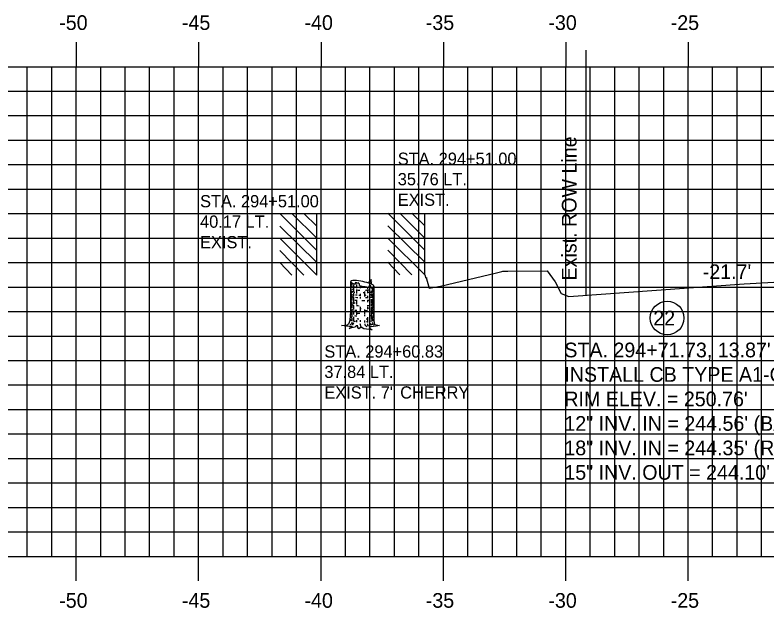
# Model space of a CAD drawing. Extents: x 859352 to 859522, y 366268 to 366378.
# Drawn here: x 859382.63 to 859413.35, y 366305.13 to 366329.35 of the extents above; entities that cross this region are included whole.
import ezdxf

# ---------------------------------------------------------------- set-up
doc = ezdxf.new("R2010")
doc.units = 0
for name, color, linetype in [('D_Drainage_Text', 7, 'Continuous'), ('D_Text_Monospaced', 7, 'Continuous'), ('D_Text_Standard', 7, 'Continuous'), ('E_ROW_Line', 7, 'Continuous'), ('H_V ANNOTATION', 7, 'Continuous'), ('MAJOR', 7, 'Continuous'), ('MINOR', 7, 'Continuous'), ('S_Buildings', 7, 'Continuous'), ('S_Roadway_Centerline', 7, 'Continuous'), ('S_Trees_Decid_NonPay', 7, 'Continuous')]:
    doc.layers.add(name, color=color, linetype=linetype)

msp = doc.modelspace()

# ---------------------------------------------------------------- linework, layer by layer
at = {"layer": 'D_Drainage_Text'}
msp.add_circle((859409.269, 366316.971), 0.687, dxfattribs=at)
at = {"layer": 'E_ROW_Line'}
msp.add_line((859405.968, 366317.905), (859405.968, 366327.905), dxfattribs=at)
at = {"layer": 'MAJOR'}
for p, q in [((859385.129, 366328.238), (859385.129, 366327.236)), ((859390.129, 366328.238), (859390.129, 366327.236)), ((859395.129, 366328.238), (859395.129, 366327.236)), ((859400.129, 366328.238), (859400.129, 366327.236)), ((859405.129, 366328.238), (859405.129, 366327.236)), ((859410.129, 366328.238), (859410.129, 366327.236)), ((859365.129, 366327.236), (859505.129, 366327.236)), ((859365.129, 366327.236), (859505.129, 366327.236)), ((859385.129, 366307.236), (859385.129, 366327.236)), ((859390.129, 366307.236), (859390.129, 366327.236)), ((859395.129, 366307.236), (859395.129, 366327.236)), ((859400.129, 366307.236), (859400.129, 366327.236)), ((859405.129, 366307.236), (859405.129, 366327.236)), ((859410.129, 366307.236), (859410.129, 366327.236)), ((859365.129, 366322.236), (859505.129, 366322.236)), ((859365.129, 366317.236), (859505.129, 366317.236)), ((859365.129, 366312.236), (859505.129, 366312.236)), ((859365.129, 366307.236), (859505.129, 366307.236)), ((859365.129, 366307.236), (859505.129, 366307.236)), ((859385.129, 366306.234), (859385.129, 366307.236)), ((859390.129, 366306.234), (859390.129, 366307.236)), ((859395.129, 366306.234), (859395.129, 366307.236)), ((859400.129, 366306.234), (859400.129, 366307.236)), ((859405.129, 366306.234), (859405.129, 366307.236)), ((859410.129, 366306.234), (859410.129, 366307.236))]:
    msp.add_line(p, q, dxfattribs=at)
at = {"layer": 'MINOR'}
for p, q in [((859383.129, 366307.236), (859383.129, 366327.236)), ((859384.129, 366307.236), (859384.129, 366327.236)), ((859386.129, 366307.236), (859386.129, 366327.236)), ((859387.129, 366307.236), (859387.129, 366327.236)), ((859388.129, 366307.236), (859388.129, 366327.236)), ((859389.129, 366307.236), (859389.129, 366327.236)), ((859391.129, 366307.236), (859391.129, 366327.236)), ((859392.129, 366307.236), (859392.129, 366327.236)), ((859393.129, 366307.236), (859393.129, 366327.236)), ((859394.129, 366307.236), (859394.129, 366327.236)), ((859396.129, 366307.236), (859396.129, 366327.236)), ((859397.129, 366307.236), (859397.129, 366327.236)), ((859398.129, 366307.236), (859398.129, 366327.236)), ((859399.129, 366307.236), (859399.129, 366327.236)), ((859401.129, 366307.236), (859401.129, 366327.236)), ((859402.129, 366307.236), (859402.129, 366327.236)), ((859403.129, 366307.236), (859403.129, 366327.236)), ((859404.129, 366307.236), (859404.129, 366327.236)), ((859406.129, 366307.236), (859406.129, 366327.236)), ((859407.129, 366307.236), (859407.129, 366327.236)), ((859408.129, 366307.236), (859408.129, 366327.236)), ((859409.129, 366307.236), (859409.129, 366327.236)), ((859411.129, 366307.236), (859411.129, 366327.236)), ((859412.129, 366307.236), (859412.129, 366327.236)), ((859413.129, 366307.236), (859413.129, 366327.236)), ((859365.129, 366326.236), (859505.129, 366326.236)), ((859365.129, 366325.236), (859505.129, 366325.236)), ((859365.129, 366324.236), (859505.129, 366324.236)), ((859365.129, 366323.236), (859505.129, 366323.236)), ((859365.129, 366321.236), (859505.129, 366321.236)), ((859365.129, 366320.236), (859505.129, 366320.236)), ((859365.129, 366319.236), (859505.129, 366319.236)), ((859365.129, 366318.236), (859505.129, 366318.236)), ((859365.129, 366316.236), (859505.129, 366316.236)), ((859365.129, 366315.236), (859505.129, 366315.236)), ((859365.129, 366314.236), (859505.129, 366314.236)), ((859365.129, 366313.236), (859505.129, 366313.236)), ((859365.129, 366311.236), (859505.129, 366311.236)), ((859365.129, 366310.236), (859505.129, 366310.236)), ((859365.129, 366309.236), (859505.129, 366309.236)), ((859365.129, 366308.236), (859505.129, 366308.236))]:
    msp.add_line(p, q, dxfattribs=at)
at = {"layer": 'S_Buildings'}
for p, q in [((859394.957, 366319.734), (859393.448, 366321.244)), ((859394.957, 366320.227), (859393.94, 366321.244)), ((859394.957, 366320.719), (859394.432, 366321.244)), ((859394.957, 366318.717), (859394.957, 366321.244)), ((859399.367, 366319.745), (859397.858, 366321.254)), ((859399.367, 366320.237), (859398.35, 366321.254)), ((859399.367, 366320.729), (859398.842, 366321.254)), ((859399.367, 366318.728), (859399.367, 366321.254)), ((859394.957, 366319.242), (859393.448, 366320.719)), ((859399.367, 366319.253), (859397.858, 366320.729)), ((859394.957, 366318.717), (859393.448, 366320.227)), ((859399.367, 366318.728), (859397.858, 366320.237)), ((859394.432, 366318.717), (859393.448, 366319.734)), ((859398.842, 366318.728), (859397.858, 366319.745)), ((859393.94, 366318.717), (859393.448, 366319.242)), ((859398.35, 366318.728), (859397.858, 366319.253))]:
    msp.add_line(p, q, dxfattribs=at)
at = {"layer": 'S_Roadway_Centerline'}
msp.add_lwpolyline([(859399.367, 366318.728), (859399.41, 366318.597), (859399.439, 366318.622), (859399.444, 366318.57), (859399.545, 366318.192), (859400.016, 366318.268), (859402.292, 366318.818), (859402.512, 366318.877), (859402.564, 366318.88), (859402.594, 366318.881), (859402.652, 366318.881), (859402.761, 366318.88), (859404.374, 366318.891), (859404.7, 366318.444), (859404.94, 366317.97), (859405.247, 366317.854), (859412.42, 366318.362), (859414.836, 366318.508)], dxfattribs=at)
at = {"layer": 'S_Trees_Decid_NonPay'}
for p, q in [((859396.394, 366318.408), (859396.394, 366318.313)), ((859396.462, 366318.321), (859396.462, 366318.021)), ((859396.581, 366318.338), (859396.581, 366318.19)), ((859396.728, 366318.292), (859396.728, 366318.185)), ((859396.394, 366318.087), (859396.394, 366318.004)), ((859396.462, 366317.992), (859396.462, 366317.861)), ((859396.581, 366318.142), (859396.581, 366317.974)), ((859396.908, 366318.056), (859396.908, 366317.856)), ((859397.025, 366318.24), (859397.025, 366318.161)), ((859397.025, 366318.075), (859397.025, 366317.99)), ((859397.112, 366318.056), (859397.112, 366317.97)), ((859397.183, 366318.229), (859397.183, 366318.178)), ((859397.183, 366318.075), (859397.183, 366317.992)), ((859397.225, 366318.235), (859397.225, 366318.017)), ((859397.252, 366318.164), (859397.252, 366318.082)), ((859397.252, 366318.013), (859397.252, 366317.883)), ((859396.394, 366317.935), (859396.394, 366317.684)), ((859396.462, 366317.827), (859396.462, 366317.546)), ((859396.581, 366317.667), (859396.581, 366317.519)), ((859396.728, 366317.957), (859396.728, 366317.871)), ((859396.728, 366317.836), (859396.728, 366317.766)), ((859397.025, 366317.879), (859397.025, 366317.778)), ((859397.025, 366317.693), (859397.025, 366317.617)), ((859397.112, 366317.899), (859397.112, 366317.778)), ((859397.112, 366317.703), (859397.112, 366317.588)), ((859397.183, 366317.957), (859397.183, 366317.883)), ((859397.183, 366317.856), (859397.183, 366317.796)), ((859397.183, 366317.743), (859397.183, 366317.562)), ((859397.225, 366317.948), (859397.225, 366317.796)), ((859397.225, 366317.691), (859397.225, 366317.613)), ((859397.252, 366317.861), (859397.252, 366317.679)), ((859396.394, 366317.601), (859396.394, 366317.371)), ((859396.462, 366317.476), (859396.462, 366317.331)), ((859396.728, 366317.432), (859396.728, 366317.21)), ((859397.025, 366317.432), (859397.025, 366317.335)), ((859397.112, 366317.527), (859397.112, 366317.445)), ((859397.112, 366317.358), (859397.112, 366317.261)), ((859397.183, 366317.531), (859397.183, 366317.449)), ((859397.183, 366317.395), (859397.183, 366317.224)), ((859397.225, 366317.586), (859397.225, 366317.479)), ((859397.225, 366317.445), (859397.225, 366317.344)), ((859397.252, 366317.632), (859397.252, 366317.385)), ((859397.252, 366317.366), (859397.252, 366317.271)), ((859396.394, 366317.3), (859396.394, 366317.14)), ((859396.394, 366317.123), (859396.394, 366317.018)), ((859396.462, 366317.261), (859396.462, 366317.119)), ((859396.581, 366317.249), (859396.581, 366317.096)), ((859396.908, 366317.319), (859396.908, 366317.132)), ((859396.908, 366317.101), (859396.908, 366317.048)), ((859397.112, 366317.132), (859397.112, 366317.033)), ((859397.183, 366317.191), (859397.183, 366316.911)), ((859397.225, 366317.318), (859397.225, 366317.136)), ((859397.254, 366317.218), (859397.253, 366316.958)), ((859396.394, 366316.981), (859396.394, 366316.857)), ((859396.462, 366316.777), (859396.42, 366316.681)), ((859396.462, 366317.018), (859396.462, 366316.837)), ((859396.581, 366316.884), (859396.581, 366316.806)), ((859396.728, 366316.876), (859396.728, 366316.81)), ((859396.908, 366316.872), (859396.908, 366316.781)), ((859397.025, 366317.01), (859397.025, 366316.786)), ((859397.112, 366316.903), (859397.112, 366316.845)), ((859397.183, 366316.859), (859397.183, 366316.833)), ((859397.223, 366316.794), (859397.258, 366316.743)), ((859397.225, 366317.033), (859397.225, 366316.841)), ((859397.252, 366316.92), (859397.252, 366316.846)), ((859396.768, 366316.59), (859396.733, 366316.736)), ((859397.305, 366316.672), (859397.238, 366316.703))]:
    msp.add_line(p, q, dxfattribs=at)
for points in [[(859397.294, 366318.272), (859397.294, 366316.86), (859397.316, 366316.712), (859397.519, 366316.668), (859397.38, 366316.633), (859397.161, 366316.615), (859397.091, 366316.571), (859397.213, 366316.483), (859396.882, 366316.526), (859396.768, 366316.59), (859396.675, 366316.53), (859396.62, 366316.609), (859396.628, 366316.645), (859396.567, 366316.647), (859396.515, 366316.59), (859396.282, 366316.539), (859396.41, 366316.627), (859396.278, 366316.629), (859395.969, 366316.666), (859396.208, 366316.697), (859396.286, 366316.755), (859396.325, 366316.876), (859396.342, 366317.23), (859396.342, 366318.464)], [(859396.706, 366318.298), (859396.698, 366318.365), (859396.674, 366318.369), (859396.665, 366318.404), (859396.634, 366318.39), (859396.62, 366318.404), (859396.595, 366318.381), (859396.572, 366318.39), (859396.56, 366318.439), (859396.552, 366318.395), (859396.521, 366318.404), (859396.518, 366318.353)], [(859397.176, 366318.229), (859397.159, 366318.29), (859397.137, 366318.279), (859397.106, 366318.313), (859397.072, 366318.235)], [(859397.198, 366318.353), (859397.195, 366318.447), (859397.18, 366318.42), (859397.18, 366318.542), (859397.159, 366318.478), (859397.145, 366318.511), (859397.128, 366318.455), (859397.112, 366318.472), (859397.093, 366318.464), (859397.074, 366318.397)], [(859396.391, 366316.815), (859396.383, 366316.738), (859396.305, 366316.689)], [(859397.028, 366316.738), (859397.034, 366316.668), (859397.097, 366316.656)], [(859397.175, 366316.703), (859397.132, 366316.738), (859397.124, 366316.786)], [(859396.916, 366316.732), (859396.916, 366316.695), (859396.967, 366316.664), (859396.985, 366316.615)], [(859397.254, 366316.72), (859397.175, 366316.703), (859397.159, 366316.66)]]:
    msp.add_lwpolyline(points, dxfattribs=at)
for centre, radius, start, end in [((859396.36, 366318.464), 0.0179, 168.1723, 184.2278), ((859396.366, 366318.464), 0.0237, 184.2278, 198.1723), ((859396.361, 366318.316), 0.0191, 163.9485, 180), ((859396.361, 366318.316), 0.0191, 180, 196.0515), ((859396.367, 366318.318), 0.0252, 196.0515, 210), ((859396.36, 366318.464), 0.0179, 152.1168, 168.1723), ((859396.365, 366318.461), 0.0237, 138.1723, 152.1168), ((859396.376, 366318.467), 0.0336, 198.1723, 216.9486), ((859396.376, 366318.323), 0.0356, 210, 228.7494), ((859396.373, 366318.454), 0.0336, 119.396, 138.1723), ((859396.423, 366318.503), 0.0935, 216.9486, 228.1723), ((859396.417, 366318.37), 0.0984, 228.7494, 240), ((859396.402, 366318.402), 0.0935, 108.1723, 119.396), ((859396.576, 366318.673), 0.322, 228.1723, 250.2902), ((859396.531, 366318.568), 0.326, 240, 248.3243), ((859396.473, 366318.185), 0.322, 86.0543, 108.1723), ((859397.313, 366320.731), 2.507, 250.2902, 251.5281), ((859396.323, 366316.005), 2.507, 78.1723, 86.0543), ((859397.313, 366320.731), 2.507, 255.9987, 258.1723), ((859397.313, 366320.731), 2.507, 258.1723, 264.5013), ((859396.323, 366316.005), 2.507, 70.2902, 78.1723), ((859397.06, 366318.062), 0.322, 48.1723, 70.2902), ((859397.212, 366318.233), 0.0935, 36.9486, 48.1723), ((859397.26, 366318.269), 0.0336, 18.1723, 36.9486), ((859397.27, 366318.272), 0.0237, 4.2278, 18.1723), ((859397.275, 366318.272), 0.0179, 348.1723, 4.2278), ((859396.361, 366318.102), 0.0191, 163.9485, 180), ((859396.361, 366318.102), 0.0191, 180, 196.0515), ((859396.367, 366318.104), 0.0252, 196.0515, 210), ((859396.361, 366317.999), 0.0191, 163.9485, 180), ((859396.361, 366317.999), 0.0191, 180, 196.0515), ((859396.367, 366318.001), 0.0252, 196.0515, 210), ((859396.376, 366318.109), 0.0356, 210, 228.7494), ((859396.376, 366318.006), 0.0356, 210, 228.7494), ((859396.417, 366318.156), 0.0984, 228.7494, 240), ((859396.417, 366318.053), 0.0984, 228.7494, 240), ((859396.531, 366318.354), 0.326, 240, 243.5719), ((859396.531, 366318.251), 0.326, 240, 243.243), ((859396.531, 366318.454), 0.326, 240.9099, 257.8036), ((859396.531, 366318.354), 0.326, 250.4167, 261.8968), ((859396.531, 366318.568), 0.326, 257.8036, 261.8968), ((859396.817, 366320.578), 2.356, 261.8968, 263.2799), ((859396.817, 366320.364), 2.356, 261.8968, 262.5519), ((859396.817, 366320.464), 2.356, 264.242, 267.3673), ((859396.817, 366320.578), 2.356, 265.24, 267.8386), ((859396.817, 366320.364), 2.356, 270.8119, 272.1981), ((859396.817, 366320.464), 2.356, 273.1481, 276.7734), ((859396.817, 366320.364), 2.356, 275.0647, 278.1032), ((859397.103, 366318.354), 0.326, 278.1032, 279.0854), ((859397.162, 366318.551), 0.322, 272.4479, 288.1723), ((859397.103, 366318.454), 0.326, 291.9506, 300), ((859397.103, 366318.354), 0.326, 291.9506, 300), ((859397.233, 366318.334), 0.0935, 288.1723, 299.396), ((859397.217, 366318.257), 0.0984, 300, 311.2506), ((859397.217, 366318.156), 0.0984, 300, 311.2506), ((859397.263, 366318.281), 0.0336, 299.396, 318.1723), ((859397.259, 366318.21), 0.0356, 311.2506, 330), ((859397.259, 366318.109), 0.0356, 311.2506, 330), ((859397.27, 366318.275), 0.0237, 318.1723, 332.1168), ((859397.268, 366318.205), 0.0252, 330, 343.9485), ((859397.268, 366318.104), 0.0252, 330, 343.9485), ((859397.275, 366318.272), 0.0179, 332.1168, 348.1723), ((859397.273, 366318.203), 0.0191, 360, 6.1128), ((859397.273, 366318.203), 0.0191, 343.9485, 360), ((859397.273, 366318.102), 0.0191, 360, 6.1128), ((859397.273, 366318.102), 0.0191, 343.9485, 360), ((859397.273, 366317.999), 0.0191, 360, 6.1128), ((859397.273, 366317.999), 0.0191, 343.9485, 360), ((859396.361, 366317.779), 0.0191, 163.9485, 180), ((859396.361, 366317.779), 0.0191, 180, 196.0515), ((859396.367, 366317.781), 0.0252, 196.0515, 210), ((859396.361, 366317.665), 0.0191, 163.9485, 180), ((859396.361, 366317.665), 0.0191, 180, 196.0515), ((859396.367, 366317.667), 0.0252, 196.0515, 210), ((859396.376, 366317.786), 0.0356, 210, 228.7494), ((859396.417, 366317.833), 0.0984, 228.7494, 240), ((859396.531, 366318.031), 0.326, 240, 245.1545), ((859396.531, 366318.146), 0.326, 245.1545, 257.8036), ((859396.531, 366318.251), 0.326, 251.6831, 257.8036), ((859396.817, 366320.041), 2.356, 262.6588, 264.7911), ((859396.817, 366320.156), 2.356, 263.2682, 265.6362), ((859396.817, 366320.261), 2.356, 263.3413, 264.9946), ((859396.817, 366320.261), 2.356, 266.5036, 267.8386), ((859396.817, 366320.041), 2.356, 269.5578, 270), ((859396.817, 366320.041), 2.356, 270, 272.414), ((859396.817, 366320.261), 2.356, 272.1981, 273.9741), ((859396.817, 366320.156), 2.356, 273.0067, 275.0647), ((859396.817, 366320.041), 2.356, 275.0647, 277.1868), ((859396.817, 366320.156), 2.356, 277.1868, 278.1032), ((859396.817, 366320.261), 2.356, 277.3838, 278.1032), ((859397.103, 366318.251), 0.326, 278.1032, 284.0382), ((859397.103, 366318.146), 0.326, 278.1032, 284.0382), ((859397.103, 366318.031), 0.326, 284.0382, 300), ((859397.103, 366318.146), 0.326, 291.9506, 300), ((859397.217, 366317.948), 0.0984, 300, 311.2506), ((859397.217, 366317.833), 0.0984, 300, 311.2506), ((859397.259, 366317.901), 0.0356, 311.2506, 330), ((859397.259, 366317.786), 0.0356, 311.2506, 330), ((859397.268, 366317.896), 0.0252, 330, 343.9485), ((859397.268, 366317.781), 0.0252, 330, 343.9485), ((859397.268, 366317.667), 0.0252, 330, 343.9485), ((859397.273, 366317.894), 0.0191, 360, 6.1128), ((859397.273, 366317.894), 0.0191, 343.9485, 360), ((859397.273, 366317.779), 0.0191, 360, 6.1128), ((859397.273, 366317.779), 0.0191, 343.9485, 360), ((859397.274, 366317.665), 0.0191, 0, 6.1128), ((859397.274, 366317.665), 0.0191, 343.9485, 360), ((859396.358, 366317.565), 0.0191, 163.9485, 180), ((859396.361, 366317.46), 0.0191, 163.9485, 180), ((859396.361, 366317.46), 0.0191, 180, 196.0515), ((859396.367, 366317.462), 0.0252, 196.0515, 210), ((859396.376, 366317.467), 0.0356, 210, 228.7494), ((859396.376, 366317.672), 0.0356, 210, 228.7494), ((859396.417, 366317.514), 0.0984, 228.7494, 240), ((859396.418, 366317.719), 0.0984, 228.7494, 240), ((859396.529, 366317.816), 0.326, 240, 256.9079), ((859396.531, 366317.711), 0.326, 240, 245.1545), ((859396.532, 366317.916), 0.326, 240, 247.8656), ((859396.532, 366317.916), 0.326, 257.6699, 261.8968), ((859396.818, 366319.926), 2.356, 261.8968, 262.8615), ((859396.815, 366319.826), 2.356, 264.3443, 266.8529), ((859396.817, 366319.721), 2.356, 267.8386, 269.0054), ((859396.815, 366319.826), 2.356, 274.9734, 277.2455), ((859396.817, 366319.721), 2.356, 275.0647, 276.428), ((859397.104, 366317.916), 0.326, 283.9036, 291.8098), ((859397.103, 366317.711), 0.326, 284.0382, 291.9506), ((859397.101, 366317.816), 0.326, 292.4049, 300), ((859397.104, 366317.916), 0.326, 297.0058, 300), ((859397.103, 366317.711), 0.326, 297.1525, 300), ((859397.215, 366317.619), 0.0984, 300, 311.2506), ((859397.217, 366317.514), 0.0984, 300, 311.2506), ((859397.218, 366317.719), 0.0984, 300, 311.2506), ((859397.256, 366317.571), 0.0356, 311.2506, 330), ((859397.259, 366317.467), 0.0356, 311.2506, 330), ((859397.259, 366317.672), 0.0356, 311.2506, 330), ((859397.265, 366317.566), 0.0252, 330, 343.9485), ((859397.271, 366317.565), 0.0191, 343.9485, 360), ((859397.268, 366317.462), 0.0252, 330, 343.9485), ((859397.271, 366317.565), 0.0191, 0, 6.1128), ((859397.273, 366317.46), 0.0191, 360, 6.1128), ((859397.273, 366317.46), 0.0191, 343.9485, 360), ((859397.273, 366317.369), 0.0191, 360, 6.1128), ((859396.357, 366317.141), 0.0191, 163.9485, 180), ((859396.357, 366317.141), 0.0191, 180, 196.0515), ((859396.363, 366317.142), 0.0252, 196.0515, 210), ((859396.372, 366317.148), 0.0356, 210, 228.7494), ((859396.413, 366317.195), 0.0984, 228.7494, 240), ((859396.527, 366317.392), 0.326, 240, 245.9375), ((859396.531, 366317.621), 0.326, 241.939, 253.9183), ((859396.813, 366319.402), 2.356, 262.2226, 264.4852), ((859396.817, 366319.631), 2.356, 262.5843, 264.4865), ((859396.817, 366319.517), 2.356, 264.242, 267.469), ((859396.817, 366319.631), 2.356, 272.1981, 275.2726), ((859396.813, 366319.402), 2.356, 277.2863, 278.1032), ((859397.099, 366317.392), 0.326, 278.1032, 284.7741), ((859397.103, 366317.507), 0.326, 284.0382, 291.9506), ((859397.213, 366317.195), 0.0984, 300, 311.2506), ((859397.254, 366317.148), 0.0356, 311.2506, 330), ((859397.264, 366317.142), 0.0252, 330, 343.9485), ((859397.269, 366317.141), 0.0191, 360, 6.1128), ((859397.269, 366317.141), 0.0191, 343.9485, 360), ((859396.346, 366316.92), 0.0191, 163.9485, 180), ((859396.346, 366316.92), 0.0191, 180, 196.0515), ((859396.352, 366316.922), 0.0252, 196.0515, 210), ((859396.361, 366316.927), 0.0356, 210, 228.7494), ((859396.352, 366317.03), 0.0191, 163.9485, 180), ((859396.352, 366317.03), 0.0191, 180, 196.0515), ((859396.358, 366317.032), 0.0252, 196.0515, 210), ((859396.367, 366317.037), 0.0356, 210, 228.7494), ((859396.403, 366316.974), 0.0984, 228.7494, 240), ((859396.408, 366317.084), 0.0984, 228.7494, 240), ((859396.517, 366317.171), 0.326, 240, 247.9161), ((859396.522, 366317.281), 0.326, 240, 241.9097), ((859396.517, 366317.171), 0.326, 260.3834, 261.8968), ((859396.803, 366319.181), 2.356, 261.8968, 263.5333), ((859396.808, 366319.291), 2.356, 264.9089, 266.8158), ((859396.808, 366319.291), 2.356, 274.1864, 275.2829), ((859396.803, 366319.181), 2.356, 274.5551, 275.4167), ((859396.803, 366319.181), 2.356, 277.5403, 278.1032), ((859397.089, 366317.171), 0.326, 278.1032, 294.7094), ((859397.094, 366317.281), 0.326, 293.6544, 300), ((859397.203, 366316.974), 0.0984, 300, 311.2506), ((859397.244, 366316.927), 0.0356, 311.2506, 330), ((859397.253, 366316.922), 0.0252, 330, 343.9485), ((859397.259, 366316.92), 0.0191, 343.9485, 360), ((859397.259, 366316.92), 0.0191, 0, 6.1128)]:
    msp.add_arc(centre, radius, start, end, dxfattribs=at)

# ---------------------------------------------------------------- texts
at = {"layer": 'D_Drainage_Text'}
for s, p in [("STA. 294+71.73, 13.87' LT. (1„)", (859405.07, 366315.365)), ('INSTALL CB TYPE A1-C', (859405.07, 366314.365)), ("RIM ELEV. = 250.76'", (859405.07, 366313.365)), ('12" INV. IN = 244.56\' (BACK)', (859405.07, 366312.365)), ('18" INV. IN = 244.35\' (RIGHT)', (859405.07, 366311.365)), ('15" INV. OUT = 244.10\'', (859405.07, 366310.365))]:
    msp.add_text(s, height=0.6, dxfattribs=at).set_placement(p)
at = {"layer": 'D_Text_Monospaced'}
for s, height, p in [('STA. 294+51.00', 0.49998, (859398.265, 366323.226)), ('35.76 LT.', 0.5, (859398.265, 366322.392)), ('STA. 294+51.00', 0.49998, (859390.189, 366321.492)), ('EXIST. ', 0.5, (859398.265, 366321.552)), ('40.17 LT.', 0.5, (859390.189, 366320.658)), ('EXIST. ', 0.5, (859390.189, 366319.818)), ('STA. 294+60.83', 0.49998, (859395.266, 366315.355)), ('37.84 LT.', 0.5, (859395.266, 366314.521)), ('EXIST. 7" CHERRY', 0.49998, (859395.266, 366313.681))]:
    msp.add_text(s, height=height, dxfattribs=at).set_placement(p)
at = {"layer": 'D_Text_Standard'}
msp.add_text("-21.7'", height=0.6, dxfattribs=at).set_placement((859410.723, 366318.561))
at = {"layer": 'E_ROW_Line'}
msp.add_text('Exist. ROW Line', height=0.6, rotation=90, dxfattribs=at).set_placement((859405.568, 366318.505))
at = {"layer": 'H_V ANNOTATION'}
for s, p in [('-50', (859384.434, 366328.736)), ('-45', (859389.447, 366328.736)), ('-40', (859394.455, 366328.736)), ('-35', (859399.41, 366328.736)), ('-30', (859404.418, 366328.736)), ('-25', (859409.415, 366328.736)), ('22', (859408.704, 366316.666)), ('-50', (859384.434, 366305.136)), ('-45', (859389.447, 366305.136)), ('-40', (859394.455, 366305.136)), ('-35', (859399.41, 366305.136)), ('-30', (859404.418, 366305.136)), ('-25', (859409.415, 366305.136))]:
    msp.add_text(s, height=0.6, dxfattribs=at).set_placement(p)

doc.saveas('drawing.dxf')
